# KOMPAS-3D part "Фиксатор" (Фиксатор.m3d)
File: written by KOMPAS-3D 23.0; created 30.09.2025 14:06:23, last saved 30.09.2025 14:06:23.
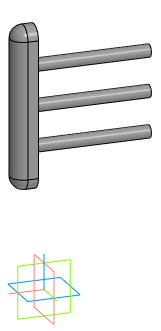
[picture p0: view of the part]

Document properties: Автор: Inspektor_Kot; Полное имя файла: I:\Autodesk Inventor Projects\ИМ-ИТ ЦД\Вариант 5\Фиксатор.m3d

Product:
- Part/product: Фиксатор

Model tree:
1. Эскиз:1  (with: Элемент выдавливания:4, Элемент выдавливания:7)
2. Элемент выдавливания:1
     Расстояние 2 = 110
3. Эскиз:2  (with: Элемент выдавливания:1)
4. Элемент выдавливания:2
     Расстояние 1 = 22.5
5. Скругление:1  (with: Элемент выдавливания:2)
     Радиус = 12.5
